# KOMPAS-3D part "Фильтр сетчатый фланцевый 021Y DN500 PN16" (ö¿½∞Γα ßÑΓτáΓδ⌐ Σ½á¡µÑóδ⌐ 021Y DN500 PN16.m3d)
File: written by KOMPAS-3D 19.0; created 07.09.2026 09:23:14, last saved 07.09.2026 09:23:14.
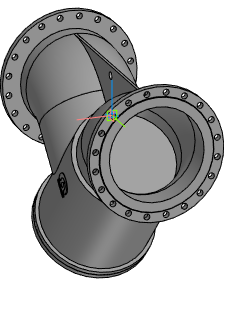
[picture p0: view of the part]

Document properties: Автор: Энергия; Полное имя файла: Z:\3.Личные\sachek\Dendor\_3D для проектировщиков\8.3 Фильтр сетчатый 021Y\021Y_STP\Фильтр сетчатый фланцевый 021Y DN500 PN16.m3d

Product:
- Part/product: Фильтр сетчатый фланцевый 021Y DN500 PN16

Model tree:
1. Операция без истории:1  (labels: Фильтр сетчатый фланцевый 021Y DN500 PN16)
